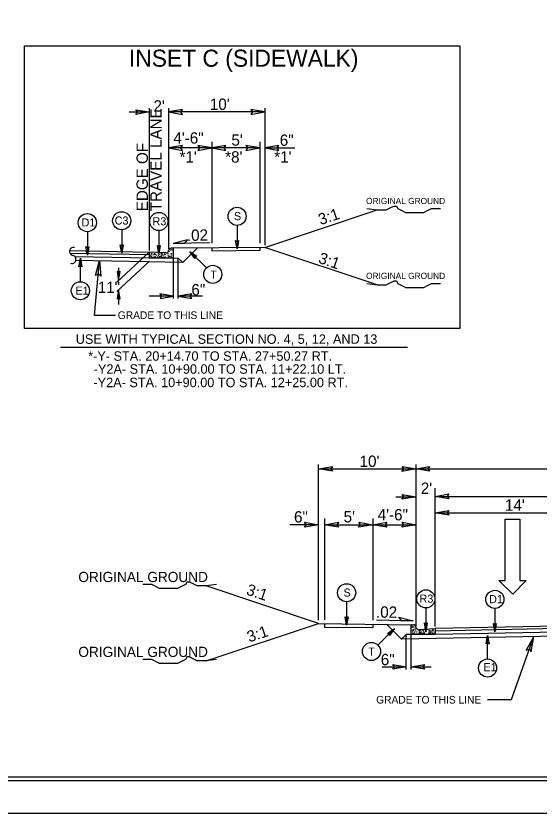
# Model space of a CAD drawing. Extents: x 958711 to 962106, y 831169 to 840840.
# Drawn here: x 958939 to 959298, y 838515 to 839063 of the extents above; entities that cross this region are included whole.
import ezdxf

# ---------------------------------------------------------------- set-up
doc = ezdxf.new("R2010")
doc.units = 0
for name, color, linetype in [('Old_Level_1', 7, 'Continuous'), ('Old_Level_11', 7, 'Continuous'), ('Old_Level_21', 7, 'Continuous'), ('Old_Level_3', 7, 'Continuous'), ('Prop Dimension Text', 7, 'Continuous'), ('Prop Lane Arrow CELL', 7, 'Continuous'), ('Sheet Plot Border Inside CELL', 7, 'Continuous'), ('Sheet Plot Border Outside CELL', 7, 'Continuous'), ('Sheet Typical CELL', 7, 'Continuous'), ('Typical ID Circle CELL', 7, 'Continuous'), ('Typical Terminator CELL', 7, 'Continuous'), ('Typical Text ID Circle CELL', 7, 'Continuous')]:
    doc.layers.add(name, color=color, linetype=linetype)

# ---------------------------------------------------------------- blocks, each defined once
blk = doc.blocks.new('Lane Arrow Through')
at = {"layer": 'Prop Lane Arrow CELL'}
for p, q in [((-3.15, 1.6), (-3.15, 3.1)), ((-3.15, 3.1), (0, 0)), ((-17.15, 1.6), (-3.15, 1.6)), ((-17.15, -1.7), (-17.15, 1.6)), ((0, 0), (-3.15, -3.2)), ((-3.15, -1.7), (-17.15, -1.7)), ((-3.15, -3.2), (-3.15, -1.7))]:
    blk.add_line(p, q, dxfattribs=at)

msp = doc.modelspace()

# ---------------------------------------------------------------- linework, layer by layer
at = {"layer": 'Old_Level_1'}
for p, q in [((959030.33, 838999.76), (959030.33, 838901.85)), ((959043.53, 838999.76), (959043.53, 838903.05)), ((959109.57, 838999.76), (959109.57, 838905.52)), ((959016.45, 838997.03), (959030.33, 838997.03)), ((959109.57, 838997.03), (959043.53, 838997.03)), ((959073.25, 838972.3), (959043.53, 838972.3)), ((959073.25, 838976.46), (959073.25, 838906.89)), ((959106.27, 838972.3), (959073.25, 838972.3)), ((959106.27, 838976.46), (959106.27, 838906.89)), ((959109.57, 838972.3), (959130.24, 838972.3)), ((959109.57, 838904.03), (959186.76, 838929.77)), ((959071.82, 838907.17), (959046.72, 838906.67)), ((958975.63, 838901.86), (959030.33, 838900.75)), ((959109.57, 838904.03), (959046.61, 838903.4)), ((959053.27, 838893.64), (959063.2, 838903.57)), ((959073.25, 838903.67), (959073.25, 838901.49)), ((959106.27, 838901.82), (959073.25, 838901.49)), ((959106.27, 838904), (959106.27, 838901.82)), ((959186.76, 838878.3), (959109.57, 838904.03)), ((958975.82, 838900.13), (959030.33, 838899.03)), ((958979.15, 838897.81), (959030.33, 838896.77)), ((959030.33, 838900.75), (959008, 838880.21)), ((959046.9, 838896.77), (959050.2, 838896.7)), ((959046.9, 838868.87), (959046.9, 838896.49)), ((959050.2, 838896.7), (959053.27, 838893.64)), ((959050.2, 838868.87), (959050.2, 838896.49)), ((958979.97, 838895.29), (959053.27, 838893.81)), ((958992.68, 838857.11), (958996.26, 838894.96)), ((959030.51, 838894.51), (959008, 838873.8)), ((959009.27, 838889.88), (959009.27, 838881.37)), ((959009.28, 838874.74), (959009.28, 838864.78)), ((959046.9, 838870.46), (959030.3, 838870.46)), ((959066.8, 838870.46), (959050.2, 838870.46)), ((959007.11, 838857.11), (958992.68, 838857.11)), ((958969.48, 838835.56), (959207.45, 838835.56)), ((959146.5, 838647.9), (959146.5, 838754.75)), ((959213.41, 838643.87), (959213.41, 838754.79)), ((959146.5, 838751.85), (959213.41, 838751.85)), ((959213.41, 838751.85), (959779.86, 838751.85)), ((959226.62, 838643.64), (959226.62, 838738.61)), ((959199.59, 838732.69), (959213.41, 838732.69)), ((959226.62, 838732.96), (959426.79, 838732.96)), ((959226.62, 838721.72), (959333.31, 838721.72)), ((959150.68, 838717.68), (959150.68, 838648.11)), ((959183.7, 838717.68), (959183.7, 838647.89)), ((959146.5, 838713.51), (959126.71, 838713.51)), ((959150.68, 838713.51), (959183.7, 838713.51)), ((959183.7, 838713.51), (959213.41, 838713.51)), ((959146.5, 838645.72), (959069.31, 838671.46)), ((959069.31, 838619.99), (959146.5, 838645.72)), ((959146.5, 838645.72), (959210.34, 838644.78)), ((959150.68, 838645.66), (959150.68, 838643.2)), ((959183.7, 838645.18), (959183.7, 838642.87)), ((959186.39, 838648.03), (959211.37, 838647.53)), ((959203.5, 838634.84), (959193.39, 838644.95)), ((959426.79, 838646.18), (959226.62, 838642.13)), ((959150.68, 838643.2), (959183.7, 838642.87)), ((959206.75, 838638.08), (959203.5, 838634.84)), ((959210.05, 838638.15), (959206.75, 838638.08)), ((959332.23, 838642.54), (959226.62, 838640.4)), ((959332.23, 838640.11), (959226.62, 838637.98)), ((959332.23, 838637.44), (959203.5, 838634.84)), ((959206.75, 838613.93), (959206.75, 838637.88)), ((959210.05, 838613.93), (959210.05, 838637.88)), ((959278.98, 838593.35), (959294.19, 838636.67)), ((959190.15, 838615.89), (959206.75, 838615.89)), ((959210.05, 838615.89), (959223.78, 838615.89)), ((959262.36, 838593.35), (959278.98, 838593.35))]:
    msp.add_line(p, q, dxfattribs=at)
msp.add_lwpolyline([(958944.68, 839042.47), (959243.42, 839042.47), (959243.42, 838848.29), (958944.68, 838848.29)], close=True, dxfattribs=at)
for centre, start, end in [((958978.39, 838901.28), 79.4545, 256.8065), ((958977.2, 838895.78), 248.3355, 78.8593)]:
    msp.add_arc(centre, 2.81, start, end, dxfattribs=at)
at = {"layer": 'Old_Level_11'}
for p, q in [((959056.45, 838909.09), (959046.72, 838906.67)), ((959046.72, 838906.67), (959054.72, 838906.83)), ((959054.72, 838906.83), (959056.45, 838909.09)), ((959203.37, 838647.68), (959201.63, 838649.94)), ((959201.63, 838649.94), (959211.37, 838647.52)), ((959211.37, 838647.52), (959203.37, 838647.68))]:
    msp.add_line(p, q, dxfattribs=at)
for points in [[(959053.14, 838998.69), (959043.53, 838997.03), (959053.2, 838995.31), (959051.97, 838997.03)], [(959099.97, 838995.38), (959109.57, 838997.03), (959099.91, 838998.74), (959101.14, 838997.03)], [(959053.14, 838973.95), (959043.53, 838972.3), (959053.2, 838970.58), (959051.97, 838972.3)], [(959063.64, 838970.64), (959073.25, 838972.3), (959063.59, 838974.01), (959064.81, 838972.3)], [(959082.86, 838973.95), (959073.25, 838972.3), (959082.92, 838970.58), (959081.69, 838972.3)], [(959096.66, 838970.64), (959106.27, 838972.3), (959096.61, 838974.01), (959097.83, 838972.3)], [(959119.18, 838973.95), (959109.57, 838972.3), (959119.24, 838970.58), (959118.01, 838972.3)], [(958993.45, 838884.61), (958996.26, 838894.96), (958997.13, 838884.21), (958995.38, 838885.72)], [(959156.1, 838750.19), (959146.5, 838751.85), (959156.16, 838753.56), (959154.94, 838751.85)], [(959203.81, 838753.51), (959213.41, 838751.85), (959203.75, 838750.13), (959204.98, 838751.85)], [(959203.81, 838734.35), (959213.41, 838732.69), (959203.75, 838730.98), (959204.98, 838732.69)], [(959136.89, 838715.17), (959146.5, 838713.51), (959136.83, 838711.8), (959138.06, 838713.51)], [(959160.28, 838711.86), (959150.68, 838713.51), (959160.34, 838715.22), (959159.12, 838713.51)], [(959174.09, 838715.17), (959183.7, 838713.51), (959174.03, 838711.8), (959175.26, 838713.51)], [(959193.3, 838711.86), (959183.7, 838713.51), (959193.36, 838715.22), (959192.13, 838713.51)], [(959203.81, 838715.17), (959213.41, 838713.51), (959203.75, 838711.8), (959204.98, 838713.51)], [(959292.49, 838626.08), (959294.19, 838636.67), (959288.98, 838627.21), (959291.18, 838627.9)]]:
    msp.add_lwpolyline(points, close=True, dxfattribs=at)
at = {"layer": 'Old_Level_21'}
for points in [[(959179.67, 838930.65), (959186.76, 838929.77), (959188.54, 838929.77), (959191.2, 838929.77), (959192.97, 838929.77), (959194.74, 838930.65), (959196.52, 838931.54), (959198.29, 838932.42), (959200.07, 838932.42), (959200.96, 838930.65), (959202.72, 838929.77), (959204.5, 838928.87), (959206.27, 838928), (959208.05, 838928), (959209.82, 838928), (959211.6, 838928), (959213.36, 838928), (959215.14, 838928), (959216.91, 838928), (959218.69, 838928), (959220.46, 838928.87), (959222.23, 838929.77), (959224, 838930.65), (959226.67, 838930.65), (959228.44, 838930.65), (959230.22, 838930.65)], [(959179.67, 838879.18), (959186.76, 838878.3), (959188.54, 838878.3), (959191.2, 838878.3), (959192.97, 838878.3), (959194.74, 838879.18), (959196.52, 838880.08), (959198.29, 838880.96), (959200.07, 838880.96), (959200.96, 838879.18), (959202.72, 838878.3), (959204.5, 838877.41), (959206.27, 838876.53), (959208.05, 838876.53), (959209.82, 838876.53), (959211.6, 838876.53), (959213.36, 838876.53), (959215.14, 838876.53), (959216.91, 838876.53), (959218.69, 838876.53), (959220.46, 838877.41), (959222.23, 838878.3), (959224, 838879.18), (959226.67, 838879.18), (959228.44, 838879.18), (959230.22, 838879.18)], [(959076.4, 838672.34), (959069.31, 838671.46), (959067.53, 838671.46), (959064.88, 838671.46), (959063.1, 838671.46), (959061.33, 838672.34), (959059.55, 838673.23), (959057.78, 838674.11), (959056, 838674.11), (959055.11, 838672.34), (959053.35, 838671.46), (959051.57, 838670.56), (959049.8, 838669.69), (959048.02, 838669.69), (959046.25, 838669.69), (959044.48, 838669.69), (959042.71, 838669.69), (959040.93, 838669.69), (959039.16, 838669.69), (959037.38, 838669.69), (959035.61, 838670.56), (959033.84, 838671.46), (959032.07, 838672.34), (959029.4, 838672.34), (959027.63, 838672.34), (959025.85, 838672.34)], [(959076.4, 838620.87), (959069.31, 838619.99), (959067.53, 838619.99), (959064.88, 838619.99), (959063.1, 838619.99), (959061.33, 838620.87), (959059.55, 838621.77), (959057.78, 838622.65), (959056, 838622.65), (959055.11, 838620.87), (959053.35, 838619.99), (959051.57, 838619.1), (959049.8, 838618.22), (959048.02, 838618.22), (959046.25, 838618.22), (959044.48, 838618.22), (959042.71, 838618.22), (959040.93, 838618.22), (959039.16, 838618.22), (959037.38, 838618.22), (959035.61, 838619.1), (959033.84, 838619.99), (959032.07, 838620.87), (959029.4, 838620.87), (959027.63, 838620.87), (959025.85, 838620.87)]]:
    msp.add_lwpolyline(points, dxfattribs=at)
at = {"layer": 'Old_Level_3'}
for p, q in [((959043.56, 838901.21), (959043.41, 838901.25)), ((959043.45, 838901.36), (959043.56, 838901.21)), ((959046.61, 838903.4), (959045.24, 838903.4)), ((959046.9, 838900.09), (959046.9, 838903.12)), ((959041.87, 838900.18), (959030.33, 838900.75)), ((959030.33, 838900.75), (959030.33, 838896.77)), ((959030.33, 838896.77), (959046.9, 838896.77)), ((959031.59, 838899.83), (959032.16, 838899.85)), ((959032.16, 838899.27), (959031.59, 838899.83)), ((959031.8, 838897.8), (959031.61, 838897.19)), ((959031.61, 838897.19), (959032.26, 838897.15)), ((959032.26, 838897.15), (959031.8, 838897.8)), ((959032.16, 838899.85), (959032.16, 838899.27)), ((959033.85, 838899.22), (959034.68, 838899.45)), ((959034.58, 838898.96), (959033.85, 838899.22)), ((959034.53, 838897.49), (959033.97, 838897.1)), ((959033.97, 838897.1), (959034.87, 838896.88)), ((959034.87, 838896.88), (959034.53, 838897.49)), ((959034.68, 838899.45), (959034.58, 838898.96)), ((959038.31, 838899.83), (959038.9, 838899.85)), ((959038.9, 838899.27), (959038.31, 838899.83)), ((959038.52, 838897.8), (959038.34, 838897.19)), ((959038.34, 838897.19), (959038.98, 838897.15)), ((959038.98, 838897.15), (959038.52, 838897.8)), ((959038.9, 838899.85), (959038.9, 838899.27)), ((959040.58, 838899.22), (959041.41, 838899.45)), ((959041.31, 838898.96), (959040.58, 838899.22)), ((959041.26, 838897.49), (959040.7, 838897.1)), ((959040.7, 838897.1), (959041.6, 838896.88)), ((959041.6, 838896.88), (959041.26, 838897.49)), ((959041.41, 838899.45), (959041.31, 838898.96)), ((959041.87, 838900.18), (959041.87, 838900.18)), ((959045.04, 838899.83), (959045.63, 838899.85)), ((959045.63, 838899.27), (959045.04, 838899.83)), ((959045.25, 838897.8), (959045.08, 838897.19)), ((959045.08, 838897.19), (959045.71, 838897.15)), ((959045.71, 838897.15), (959045.25, 838897.8)), ((959045.63, 838899.85), (959045.63, 838899.27)), ((959046.9, 838896.77), (959046.9, 838900.09)), ((959210.05, 838641.46), (959210.05, 838644.5)), ((959210.34, 838644.78), (959211.71, 838644.78)), ((959210.05, 838638.15), (959210.05, 838641.46)), ((959226.62, 838638.15), (959210.05, 838638.15)), ((959211.24, 838638.53), (959211.7, 838639.18)), ((959211.87, 838638.56), (959211.24, 838638.53)), ((959211.32, 838641.23), (959211.32, 838640.65)), ((959211.91, 838641.2), (959211.32, 838641.23)), ((959211.32, 838640.65), (959211.91, 838641.2)), ((959211.7, 838639.18), (959211.87, 838638.56)), ((959213.5, 838642.74), (959213.39, 838642.59)), ((959213.39, 838642.59), (959213.53, 838642.62)), ((959215.08, 838641.56), (959226.62, 838642.13)), ((959215.08, 838641.56), (959215.08, 838641.56)), ((959215.35, 838638.26), (959215.69, 838638.87)), ((959216.25, 838638.47), (959215.35, 838638.26)), ((959215.54, 838640.83), (959215.63, 838640.34)), ((959216.37, 838640.59), (959215.54, 838640.83)), ((959215.63, 838640.34), (959216.37, 838640.59)), ((959215.69, 838638.87), (959216.25, 838638.47)), ((959217.97, 838638.53), (959218.43, 838639.18)), ((959218.6, 838638.56), (959217.97, 838638.53)), ((959218.05, 838641.23), (959218.05, 838640.65)), ((959218.64, 838641.2), (959218.05, 838641.23)), ((959218.05, 838640.65), (959218.64, 838641.2)), ((959218.43, 838639.18), (959218.6, 838638.56)), ((959222.08, 838638.26), (959222.42, 838638.87)), ((959222.98, 838638.47), (959222.08, 838638.26)), ((959222.27, 838640.83), (959222.37, 838640.34)), ((959223.1, 838640.59), (959222.27, 838640.83)), ((959222.37, 838640.34), (959223.1, 838640.59)), ((959222.42, 838638.87), (959222.98, 838638.47)), ((959224.69, 838638.53), (959225.15, 838639.18)), ((959225.34, 838638.56), (959224.69, 838638.53)), ((959224.78, 838641.23), (959224.78, 838640.65)), ((959225.36, 838641.2), (959224.78, 838641.23)), ((959224.78, 838640.65), (959225.36, 838641.2)), ((959225.15, 838639.18), (959225.34, 838638.56)), ((959226.62, 838642.13), (959226.62, 838638.15))]:
    msp.add_line(p, q, dxfattribs=at)
for centre in [(959043.93, 838901.27), (959043.96, 838902.56), (959044.91, 838901.76), (959045.07, 838902.69), (959045.93, 838902.32), (959046.08, 838901.58), (959046.84, 838901.67), (959030.53, 838899.36), (959030.81, 838900.47), (959030.87, 838897.89), (959031.03, 838898.44), (959031.83, 838898.78), (959032.07, 838898.23), (959032.59, 838898.69), (959032.75, 838900.29), (959032.75, 838897.16), (959033.18, 838898.02), (959033.26, 838896.91), (959033.29, 838899.09), (959033.48, 838898.2), (959033.57, 838897.68), (959034, 838899.67), (959034.52, 838898.2), (959035.17, 838898.47), (959035.45, 838899.83), (959036.12, 838897.59), (959036.52, 838899.43), (959036.55, 838898.63), (959036.65, 838898.36), (959036.8, 838897.43), (959037.26, 838899.36), (959037.6, 838897.89), (959037.75, 838898.44), (959038.55, 838898.78), (959038.8, 838898.23), (959039.32, 838898.69), (959039.48, 838897.16), (959039.91, 838898.02), (959039.99, 838896.91), (959040.02, 838899.09), (959040.21, 838898.2), (959040.3, 838897.68), (959040.73, 838899.67), (959041.25, 838898.2), (959041.9, 838898.47), (959042.18, 838899.83), (959042.85, 838897.59), (959043.16, 838900.44), (959043.25, 838899.43), (959043.28, 838898.63), (959043.38, 838898.36), (959043.53, 838897.43), (959043.99, 838899.36), (959044.27, 838900.47), (959044.33, 838897.89), (959044.48, 838898.44), (959045.28, 838898.78), (959045.53, 838898.23), (959046.05, 838898.69), (959046.21, 838900.29), (959046.21, 838897.16), (959046.64, 838898.02), (959046.72, 838896.91), (959046.75, 838899.09), (959211.02, 838643.69), (959211.88, 838644.06), (959212.99, 838643.94), (959210.11, 838643.05), (959210.2, 838640.46), (959210.23, 838638.29), (959210.31, 838639.39), (959210.74, 838641.66), (959210.74, 838638.53), (959210.87, 838642.96), (959210.9, 838640.06), (959211.42, 838639.61), (959211.67, 838640.16), (959212.04, 838643.14), (959212.47, 838639.82), (959212.62, 838639.27), (959212.68, 838641.85), (959212.96, 838640.74), (959213.02, 838642.65), (959213.42, 838638.81), (959213.57, 838639.73), (959213.67, 838640), (959213.7, 838640.8), (959213.79, 838641.82), (959214.1, 838638.96), (959214.77, 838641.2), (959215.05, 838639.85), (959215.7, 838639.58), (959216.22, 838641.05), (959216.65, 838639.06), (959216.74, 838639.58), (959216.93, 838640.46), (959216.96, 838638.29), (959217.04, 838639.39), (959217.47, 838638.53), (959217.63, 838640.06), (959218.15, 838639.61), (959218.39, 838640.16), (959219.19, 838639.82), (959219.35, 838639.27), (959219.69, 838640.74), (959220.15, 838638.81), (959220.3, 838639.73), (959220.39, 838640), (959220.43, 838640.8), (959220.83, 838638.96), (959221.5, 838641.2), (959221.78, 838639.85), (959222.42, 838639.58), (959222.95, 838641.05), (959223.38, 838639.06), (959223.47, 838639.58), (959223.66, 838640.46), (959223.69, 838638.29), (959223.77, 838639.39), (959224.2, 838641.66), (959224.2, 838638.53), (959224.35, 838640.06), (959224.88, 838639.61), (959225.12, 838640.16), (959225.92, 838639.82), (959226.08, 838639.27), (959226.14, 838641.85), (959226.42, 838640.74)]:
    msp.add_circle(centre, 0.0432, dxfattribs=at)
for centre, radius, start, end in [((959041.95, 838901.81), 1.64, 267.1376, 358.9266), ((959045.24, 838901.75), 1.66, 90, 178.9266), ((959046.61, 838903.12), 0.287, 0, 90), ((959046.72, 838903.33), 0.0432, 169.6531, 280.3469), ((959036.43, 838900.44), 0.0432, 164.1199, 10.1626), ((959039.48, 838900.29), 0.0432, 162.062, 12.2205), ((959046.94, 838898.2), 0.0432, 150.4173, 209.5827), ((959210.34, 838644.5), 0.287, 90, 180), ((959210.23, 838644.71), 0.0432, 259.6531, 10.3469), ((959211.71, 838643.13), 1.66, 1.0734, 90), ((959210.01, 838639.58), 0.0432, 330.4173, 29.5827), ((959215, 838643.19), 1.64, 181.0734, 272.8624), ((959217.47, 838641.66), 0.0432, 167.7795, 17.938), ((959220.52, 838641.82), 0.0432, 169.8374, 15.8801)]:
    msp.add_arc(centre, radius, start, end, dxfattribs=at)
at = {"layer": 'Sheet Plot Border Inside CELL'}
msp.add_lwpolyline([(960390.3, 839592.94), (958723.8, 839592.94), (958723.8, 838537.84), (960390.3, 838537.84)], close=True, dxfattribs=at)
at = {"layer": 'Sheet Plot Border Outside CELL'}
msp.add_lwpolyline([(960394.8, 839615.39), (958710.8, 839615.39), (958710.8, 838515.39), (960394.8, 838515.39)], close=True, dxfattribs=at)
at = {"layer": 'Sheet Typical CELL'}
msp.add_lwpolyline([(960377.8, 839590.39), (958877.8, 839590.39), (958877.8, 838540.39), (960377.8, 838540.39)], close=True, dxfattribs=at)
at = {"layer": 'Typical ID Circle CELL'}
for p, q in [((959090.6, 838919.11), (959090.6, 838903.03)), ((958987.81, 838914.8), (958987.81, 838898.71)), ((959011.41, 838916.08), (959011.41, 838900)), ((959036.89, 838915.57), (959036.89, 838899.48)), ((959069.5, 838889.87), (959058.12, 838901.24)), ((958983.02, 838880.42), (958983.02, 838896.51)), ((959165.78, 838660.52), (959165.78, 838644.43)), ((959220.17, 838656.31), (959220.17, 838640.22)), ((959267.53, 838655.96), (959267.53, 838639.88)), ((959187.21, 838630.81), (959198.58, 838642.19)), ((959262.52, 838621.23), (959262.52, 838637.31))]:
    msp.add_line(p, q, dxfattribs=at)
for centre in [(959011.41, 838922.31), (959090.6, 838925.34), (958987.81, 838921.02), (959036.89, 838921.79), (959073.9, 838885.46), (958983.02, 838874.2), (959165.78, 838666.74), (959220.17, 838662.54), (959267.53, 838662.19), (959182.81, 838626.41), (959262.52, 838615)]:
    msp.add_circle(centre, 6.23, dxfattribs=at)
at = {"layer": 'Typical Terminator CELL'}
for points in [[(959021.1, 838998.62), (959030.33, 838997.03), (959021.05, 838995.39), (959022.23, 838997.03)], [(959091.6, 838908.79), (959090.6, 838903.03), (959089.58, 838908.82), (959090.6, 838908.09)], [(958988.81, 838904.48), (958987.81, 838898.71), (958986.79, 838904.51), (958987.81, 838903.77)], [(959012.4, 838905.76), (959011.41, 838900), (959010.39, 838905.79), (959011.41, 838905.05)], [(959037.88, 838905.25), (959036.89, 838899.48), (959035.86, 838905.28), (959036.89, 838904.54)], [(959061.49, 838896.46), (959058.12, 838901.24), (959062.94, 838897.87), (959061.7, 838897.66)], [(958982.02, 838890.75), (958983.02, 838896.51), (958984.04, 838890.72), (958983.02, 838891.45)], [(959008.22, 838887.44), (959009.27, 838881.37), (959010.34, 838887.47), (959009.27, 838886.7)], [(959010.33, 838868.67), (959009.28, 838874.74), (959008.2, 838868.64), (959009.28, 838869.41)], [(959037.68, 838868.87), (959046.9, 838870.46), (959037.63, 838872.1), (959038.81, 838870.46)], [(959059.42, 838872.05), (959050.2, 838870.46), (959059.48, 838868.82), (959058.3, 838870.46)], [(959222.64, 838750.26), (959213.41, 838751.85), (959222.69, 838753.49), (959221.51, 838751.85)], [(959235.85, 838731.37), (959226.62, 838732.96), (959235.9, 838734.6), (959234.72, 838732.96)], [(959235.85, 838720.13), (959226.62, 838721.72), (959235.9, 838723.36), (959234.72, 838721.72)], [(959166.77, 838650.19), (959165.78, 838644.43), (959164.75, 838650.22), (959165.78, 838649.49)], [(959221.16, 838645.99), (959220.17, 838640.22), (959219.15, 838646.02), (959220.17, 838645.28)], [(959268.52, 838645.64), (959267.53, 838639.88), (959266.5, 838645.67), (959267.53, 838644.94)], [(959193.8, 838638.82), (959198.58, 838642.19), (959195.21, 838637.37), (959195, 838638.61)], [(959261.52, 838631.55), (959262.52, 838637.31), (959263.54, 838631.52), (959262.52, 838632.25)], [(959197.52, 838617.47), (959206.75, 838615.89), (959197.47, 838614.25), (959198.65, 838615.89)], [(959219.27, 838614.3), (959210.05, 838615.89), (959219.32, 838617.53), (959218.14, 838615.89)]]:
    msp.add_lwpolyline(points, close=True, dxfattribs=at)

# ---------------------------------------------------------------- block references
at = {"layer": 'Old_Level_1', "xscale": 3, "yscale": 3, "rotation": -90.00000000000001}
msp.add_blockref('Lane Arrow Through', (959279.78, 838665.74), dxfattribs=at)

# ---------------------------------------------------------------- texts
at = {"layer": 'Old_Level_1'}
for s, height, p in [('INSET C (SIDEWALK)', 11.7158, (959016.33, 839028.13)), ('GRADE TO THIS LINE', 5.2473, (959008.71, 838854.81)), ('USE WITH TYPICAL SECTION NO. 4, 5, 12, AND 13', 6.5088, (958979.86, 838837.75)), ('*-Y- STA. 20+14.70 TO STA. 27+50.27 RT. ', 6.5088, (958988.4, 838826.12)), ('-Y2A- STA. 10+90.00 TO STA. 11+22.10 LT. ', 6.5088, (958992.19, 838817.19)), ('-Y2A- STA. 10+90.00 TO STA. 12+25.00 RT. ', 6.5088, (958992, 838807.97)), ('GRADE TO THIS LINE', 5.2473, (959186.05, 838590.62))]:
    msp.add_text(s, height=height, dxfattribs=at).set_placement(p)
at = {"layer": 'Old_Level_21'}
for height, p in [(4.2722, (959179.12, 838933.76)), (4.2722, (959179.12, 838882.3)), (7, (958981.63, 838674.09)), (7, (958981.63, 838622.62))]:
    msp.add_text('ORIGINAL GROUND', height=height, dxfattribs=at).set_placement(p)
at = {"layer": 'Old_Level_3'}
for s, p in [("2'", (959033.2, 838997.28)), ("10'", (959071.91, 838998.48)), ('4\'-6"', (959046.84, 838975.27)), ("5'", (959086.71, 838973.86)), ('6"', (959119.89, 838973.77)), ("*1'", (959051.07, 838962.27)), ("*8'", (959082.41, 838962.27)), ("*1'", (959116.09, 838962.27)), ("10'", (959174.67, 838753.18)), ("2'", (959216.68, 838734.64)), ('6"', (959129.66, 838714.99)), ("5'", (959163.7, 838715.07)), ('4\'-6"', (959187.09, 838716.48))]:
    msp.add_text(s, height=7.801, dxfattribs=at).set_placement(p)
for s, height, rotation, p in [('TRAVEL LANE', 7.8009, 90, (959038.81, 838928.83)), ('EDGE OF', 7.801, 90, (959029.38, 838928.83)), ('3:1', 7.801, 18.4348, (959147.87, 838919.22)), ('3:1', 7.801, 341.0454, (959145.82, 838893.53)), ('3:1', 7.801, 341.5652, (959096.31, 838665.69)), ('.02', 7.801, 359.4336, (959185.9, 838649.64)), ('3:1', 7.801, 18.4348, (959098.9, 838632.51))]:
    msp.add_text(s, height=height, rotation=rotation, dxfattribs=at).set_placement(p)
at = {"layer": 'Prop Dimension Text'}
for s, rotation, p in [('.02', 1.1839, (959056.2, 838908.37)), ('11"', 0, (958994.96, 838872.71)), ('6"', 0, (959059.23, 838871.06)), ("14'", 0, (959274.48, 838723.08)), ('6"', 0, (959189.22, 838616.96))]:
    msp.add_text(s, height=7.801, rotation=rotation, dxfattribs=at).set_placement(p)
at = {"layer": 'Typical Text ID Circle CELL'}
for s, height, p in [('S', 5.57, (959088.43, 838922.71)), ('D1', 5.572, (958983.82, 838918.39)), ('C3', 5.572, (959006.52, 838919.68)), ('R3', 5.572, (959032.51, 838919.16)), ('T', 5.57, (959072.19, 838882.49)), ('E1', 5.572, (958979.62, 838871.51)), ('S', 5.57, (959163.61, 838664.11)), ('R3', 5.572, (959215.79, 838659.91)), ('D1', 5.572, (959263.54, 838659.56)), ('E1', 5.572, (959259.63, 838612.87))]:
    msp.add_text(s, height=height, dxfattribs=at).set_placement(p)
msp.add_text('T', height=5.57, rotation=360, dxfattribs=at).set_placement((959180.65, 838623.52))

doc.saveas('drawing.dxf')
